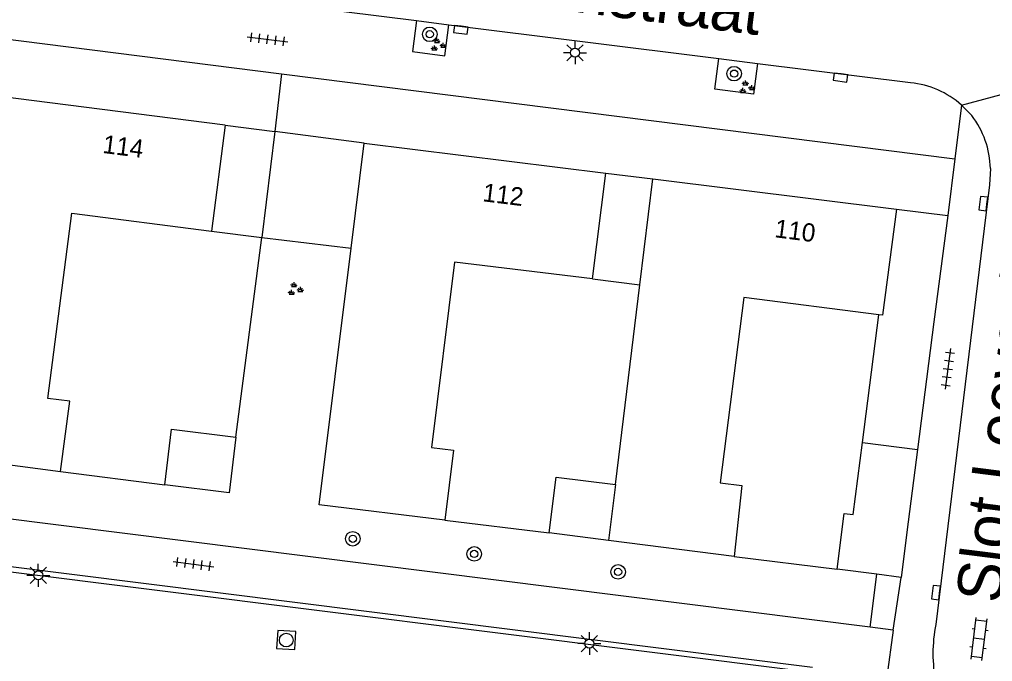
# Model space of a CAD drawing. Extents: x 131000 to 133014, y 396499 to 399001.
# Drawn here: x 131670.9 to 131724.4, y 396677.1 to 396712.4 of the extents above; entities that cross this region are included whole.
import ezdxf

# ---------------------------------------------------------------- set-up
doc = ezdxf.new("R2010")
doc.units = 0
for name, color, linetype in [('gg-afsc-erfafscheiding', 7, 'Continuous'), ('gg-afsc-hekwerk', 7, 'Continuous'), ('gg-afsc-muur', 7, 'Continuous'), ('gg-anno-huisnummerreeks BGT', 7, 'Continuous'), ('gg-anno-openbare ruimte label', 7, 'Continuous'), ('gg-bbg-bijgebouw', 7, 'Continuous'), ('gg-bbg-gedigitaliseerde bebouwing', 7, 'Continuous'), ('gg-bbg-gedigitaliseerde bijgebouw', 7, 'Continuous'), ('gg-bbg-hoofdgebouw', 7, 'Continuous'), ('gg-bbg-luifel en loopbrug', 7, 'Continuous'), ('gg-bbg-tussenscheiding', 7, 'Continuous'), ('gg-knt-verharding', 7, 'Continuous'), ('gt-grn-groengrens', 7, 'Continuous'), ('gt-grn-vlakafsluiter', 7, 'Continuous'), ('gt-grn-weggrens', 7, 'Continuous'), ('gt-symb-boom', 7, 'Continuous'), ('gt-symb-groenvak', 7, 'Continuous'), ('gt-symb-klinker verharding', 7, 'Continuous'), ('gt-symb-kolk', 7, 'Continuous'), ('gt-symb-lichtmast', 7, 'Continuous'), ('gt-symb-rioolschacht', 7, 'Continuous'), ('gt-symb-tegel verharding', 7, 'Continuous')]:
    doc.layers.add(name, color=color, linetype=linetype)

# ---------------------------------------------------------------- blocks, each defined once
blk = doc.blocks.new('gt0-KL1')
at = {"layer": 'gt-symb-klinker verharding'}
for p, q in [((-1.15, 0.3), (1.15, 0.3)), ((-1, -0.3), (-1, 0.3)), ((-0.5, 0.3), (-0.5, 0.45)), ((0, -0.3), (0, 0.3)), ((0.5, 0.3), (0.5, 0.45)), ((1, -0.3), (1, 0.3)), ((-1.15, -0.3), (1.15, -0.3)), ((-0.5, -0.45), (-0.5, -0.3)), ((0.5, -0.45), (0.5, -0.3))]:
    blk.add_line(p, q, dxfattribs=at)
blk = doc.blocks.new('gt0-KOLK')
at = {"layer": 'gt-symb-kolk'}
blk.add_lwpolyline([(0, 0), (0.375, 0), (0.375, 0.4), (-0.375, 0.4), (-0.375, 0), (0, 0)], dxfattribs=at)
blk = doc.blocks.new('gt0-TEG1')
at = {"layer": 'gt-symb-tegel verharding'}
for p, q in [((-1.125, 0), (1.125, 0)), ((-0.9, -0.25), (-0.9, 0.25)), ((-0.45, -0.25), (-0.45, 0.25)), ((0, -0.25), (0, 0.25)), ((0.45, -0.25), (0.45, 0.25)), ((0.9, -0.25), (0.9, 0.25))]:
    blk.add_line(p, q, dxfattribs=at)
blk = doc.blocks.new('gt0-LMAST')
at = {"layer": 'gt-symb-lichtmast'}
for p, q in [((-0.005, 0.246), (-0.005, 0.621)), ((-0.182, 0.173), (-0.447, 0.438)), ((0.172, 0.173), (0.437, 0.438)), ((-0.255, -0.004), (-0.63, -0.004)), ((-0.182, -0.181), (-0.447, -0.446)), ((-0.005, -0.254), (-0.005, -0.629)), ((0.437, -0.446), (0.172, -0.181)), ((0.245, -0.004), (0.62, -0.004))]:
    blk.add_line(p, q, dxfattribs=at)
blk.add_circle((-0.005, -0.004), 0.25, dxfattribs=at)
blk = doc.blocks.new('gt0-BOOM')
at = {"layer": 'gt-symb-boom'}
for radius in [0.4, 0.2]:
    blk.add_circle((0, 0), radius, dxfattribs=at)
blk = doc.blocks.new('gt0-GRVAK')
at = {"layer": 'gt-symb-groenvak'}
for p, q in [((-0.11, 0.189), (-0.228, 0.24)), ((-0.182, 0.153), (0.088, 0.153)), ((-0.091, 0.211), (-0.156, 0.322)), ((-0.047, 0.214), (-0.047, 0.393)), ((-0.004, 0.211), (0.061, 0.322)), ((0.015, 0.189), (0.133, 0.24)), ((0.262, -0.052), (0.197, 0.059)), ((0.305, -0.049), (0.305, 0.13)), ((0.349, -0.052), (0.414, 0.059)), ((-0.245, -0.228), (-0.363, -0.177)), ((-0.318, -0.264), (-0.047, -0.264)), ((-0.226, -0.206), (-0.291, -0.095)), ((-0.183, -0.203), (-0.183, -0.024)), ((-0.139, -0.206), (-0.074, -0.095)), ((-0.12, -0.228), (-0.002, -0.177)), ((0.243, -0.074), (0.125, -0.023)), ((0.17, -0.11), (0.441, -0.11)), ((0.368, -0.074), (0.486, -0.023))]:
    blk.add_line(p, q, dxfattribs=at)
blk = doc.blocks.new('gt0-RS')
at = {"layer": 'gt-symb-rioolschacht'}
blk.add_lwpolyline([(-0.5, -0.5), (0.5, -0.5), (0.5, 0.5), (-0.5, 0.5)], close=True, dxfattribs=at)
blk.add_circle((0, 0), 0.375, dxfattribs=at)

msp = doc.modelspace()

# ---------------------------------------------------------------- linework, layer by layer
at = {"layer": 'gg-afsc-erfafscheiding'}
for p, q in [((131673.18, 396687.58), (131678.91, 396686.84)), ((131694.29, 396684.9), (131700.02, 396684.2)), ((131710.17, 396682.91), (131715.83, 396682.21)), ((131718.91, 396678.86), (131719.35, 396681.76))]:
    msp.add_line(p, q, dxfattribs=at)
at = {"layer": 'gg-afsc-hekwerk'}
msp.add_line((131636.551, 396686.309), (131714.442, 396676.549), dxfattribs=at)
at = {"layer": 'gg-afsc-muur'}
msp.add_line((131682.8, 396689.47), (131684.24, 396700.42), dxfattribs=at)
at = {"layer": 'gg-bbg-bijgebouw'}
for p, q in [((131720.25, 396688.787), (131719.74, 396684.82)), ((131715.83, 396682.21), (131716.22, 396685.27)), ((131719.74, 396684.82), (131719.35, 396681.76)), ((131703.274, 396683.786), (131700.02, 396684.2)), ((131718.007, 396681.932), (131715.83, 396682.21)), ((131719.35, 396681.76), (131718.007, 396681.932))]:
    msp.add_line(p, q, dxfattribs=at)
for points in [[(131678.91, 396686.84), (131679.28, 396689.9), (131682.8, 396689.47)], [(131682.8, 396689.47), (131682.43, 396686.41), (131678.91, 396686.84)], [(131700.02, 396684.2), (131700.39, 396687.26), (131703.65, 396686.86)]]:
    msp.add_lwpolyline(points, dxfattribs=at)
at = {"layer": 'gg-bbg-gedigitaliseerde bebouwing'}
msp.add_line((131719.082, 396701.981), (131718.322, 396696.153), dxfattribs=at)
at = {"layer": 'gg-bbg-gedigitaliseerde bijgebouw'}
for p, q in [((131716.716, 396685.207), (131717.223, 396689.174)), ((131717.223, 396689.174), (131720.25, 396688.787)), ((131716.22, 396685.27), (131716.716, 396685.207))]:
    msp.add_line(p, q, dxfattribs=at)
at = {"layer": 'gg-bbg-hoofdgebouw'}
for p, q in [((131682.217, 396706.596), (131668.855, 396708.295)), ((131682.217, 396706.596), (131681.471, 396700.775)), ((131689.131, 396699.832), (131689.85, 396705.61)), ((131689.85, 396705.61), (131703.125, 396703.962)), ((131702.403, 396698.148), (131703.125, 396703.962)), ((131704.99, 396697.83), (131705.7, 396703.642)), ((131705.7, 396703.642), (131719.082, 396701.981)), ((131703.65, 396686.86), (131704.99, 396697.83)), ((131718.322, 396696.153), (131718.117, 396696.179)), ((131666.307, 396688.469), (131673.18, 396687.58)), ((131710.17, 396682.91), (131703.274, 396683.786))]:
    msp.add_line(p, q, dxfattribs=at)
for points in [[(131673.18, 396687.58), (131673.68, 396691.43), (131672.48, 396691.59), (131673.79, 396701.76), (131681.471, 396700.775)], [(131694.29, 396684.9), (131687.38, 396685.75), (131689.131, 396699.832)], [(131702.403, 396698.148), (131694.81, 396699.08), (131693.56, 396688.9), (131694.76, 396688.75), (131694.29, 396684.9)], [(131718.117, 396696.179), (131710.71, 396697.13), (131709.4, 396686.96), (131710.6, 396686.8), (131710.17, 396682.91)]]:
    msp.add_lwpolyline(points, dxfattribs=at)
at = {"layer": 'gg-bbg-luifel en loopbrug'}
for p, q in [((131682.217, 396706.596), (131684.94, 396706.25)), ((131684.94, 396706.25), (131684.24, 396700.42)), ((131703.125, 396703.962), (131705.7, 396703.642)), ((131719.082, 396701.981), (131721.91, 396701.63)), ((131721.91, 396701.63), (131721.15, 396695.79)), ((131681.471, 396700.775), (131684.24, 396700.42)), ((131702.403, 396698.148), (131704.99, 396697.83)), ((131717.223, 396689.174), (131718.117, 396696.179)), ((131721.15, 396695.79), (131720.25, 396688.787))]:
    msp.add_line(p, q, dxfattribs=at)
at = {"layer": 'gg-bbg-tussenscheiding'}
msp.add_line((131703.65, 396686.86), (131703.274, 396683.786), dxfattribs=at)
at = {"layer": 'gg-knt-verharding'}
for p, q in [((131678.785, 396714.087), (131692.725, 396712.337)), ((131662.423, 396712.313), (131685.321, 396709.421)), ((131692.725, 396712.337), (131694.506, 396712.113)), ((131694.506, 396712.113), (131709.33, 396710.252)), ((131709.33, 396710.252), (131711.45, 396709.986)), ((131711.45, 396709.986), (131719.86, 396708.93)), ((131685.321, 396709.421), (131722.3, 396704.75)), ((131722.669, 396707.699), (131723.22, 396707.13)), ((131722.3, 396704.75), (131721.91, 396701.63)), ((131717.638, 396679.02), (131634.188, 396689.528)), ((131636.588, 396686.616), (131714.476, 396676.821)), ((131718.91, 396678.86), (131717.638, 396679.02))]:
    msp.add_line(p, q, dxfattribs=at)
for points in [[(131692.725, 396712.337), (131692.512, 396710.639), (131694.291, 396710.397), (131694.506, 396712.113)], [(131711.45, 396709.986), (131711.237, 396708.289), (131709.118, 396708.565), (131709.33, 396710.252)], [(131724.251, 396704.214), (131724.19, 396703.31), (131721.25, 396679.18)]]:
    msp.add_lwpolyline(points, dxfattribs=at)
for centre, radius, start, end in [((131719.344, 396703.933), 5.023, 48.5613, 84.1094), ((131719.279, 396704.096), 4.973, 1.356, 37.5877), ((131729.323, 396677.575), 8.231, 168.7556, 191.2444)]:
    msp.add_arc(centre, radius, start, end, dxfattribs=at)
at = {"layer": 'gt-grn-groengrens'}
for p, q in [((131689.85, 396705.61), (131684.94, 396706.25)), ((131684.24, 396700.42), (131689.131, 396699.832)), ((131717.638, 396679.02), (131718.007, 396681.932))]:
    msp.add_line(p, q, dxfattribs=at)
at = {"layer": 'gt-grn-vlakafsluiter'}
msp.add_line((131685.321, 396709.421), (131684.94, 396706.25), dxfattribs=at)
at = {"layer": 'gt-grn-weggrens'}
for p, q in [((131722.669, 396707.699), (131728.591, 396709.276)), ((131722.669, 396707.699), (131722.3, 396704.75)), ((131718.91, 396678.86), (131718.553, 396676.308))]:
    msp.add_line(p, q, dxfattribs=at)

# ---------------------------------------------------------------- block references
at = {"layer": 'gt-symb-boom'}
for p in [(131693.454, 396711.586), (131710.171, 396709.425), (131689.227, 396683.882), (131695.898, 396683.048), (131703.799, 396682.06)]:
    msp.add_blockref('gt0-BOOM', p, dxfattribs=at)
at = {"layer": 'gt-symb-groenvak'}
for p in [(131693.894, 396710.989), (131710.842, 396708.661), (131686.047, 396697.579)]:
    msp.add_blockref('gt0-GRVAK', p, dxfattribs=at)
at = {"layer": 'gt-symb-klinker verharding', "rotation": 83.05258934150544}
msp.add_blockref('gt0-KL1', (131723.625, 396678.38), dxfattribs=at)
at = {"layer": 'gt-symb-kolk'}
for p, rotation in [((131695.188, 396712.03), 172.64762064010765), ((131716.045, 396709.409), 172.46974664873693), ((131724.06, 396702.266), 83.05258934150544), ((131721.457, 396680.9), 82.99574075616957)]:
    msp.add_blockref('gt0-KOLK', p, dxfattribs=dict(at, rotation=rotation))
at = {"layer": 'gt-symb-lichtmast'}
for p in [(131701.438, 396710.577), (131671.962, 396681.877), (131702.226, 396678.127)]:
    msp.add_blockref('gt0-LMAST', p, dxfattribs=at)
at = {"layer": 'gt-symb-rioolschacht', "rotation": -3.2116257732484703}
msp.add_blockref('gt0-RS', (131685.574, 396678.319), dxfattribs=at)
at = {"layer": 'gt-symb-tegel verharding'}
for p, rotation in [((131684.545, 396711.31), -7.125016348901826), ((131721.91, 396693.209), -97.35237935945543), ((131680.484, 396682.488), -7.125016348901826)]:
    msp.add_blockref('gt0-TEG1', p, dxfattribs=dict(at, rotation=rotation))

# ---------------------------------------------------------------- texts
at = {"layer": 'gg-anno-huisnummerreeks BGT'}
for s, rotation, p in [('114', 352.7, (131675.452, 396705.075)), ('112', 353, (131696.323, 396702.421)), ('110', 352.7, (131712.357, 396700.447))]:
    msp.add_text(s, height=1, rotation=rotation, dxfattribs=at).set_placement(p)
at = {"layer": 'gg-anno-openbare ruimte label'}
for rotation, p in [(352.8, (131680.53, 396715.456)), (82.8, (131724.828, 396680.284))]:
    msp.add_text('Slot Loevesteinstraat', height=2.5, rotation=rotation, dxfattribs=at).set_placement(p)

doc.saveas('drawing.dxf')
